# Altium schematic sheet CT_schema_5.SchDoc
size 257 x 245 mm
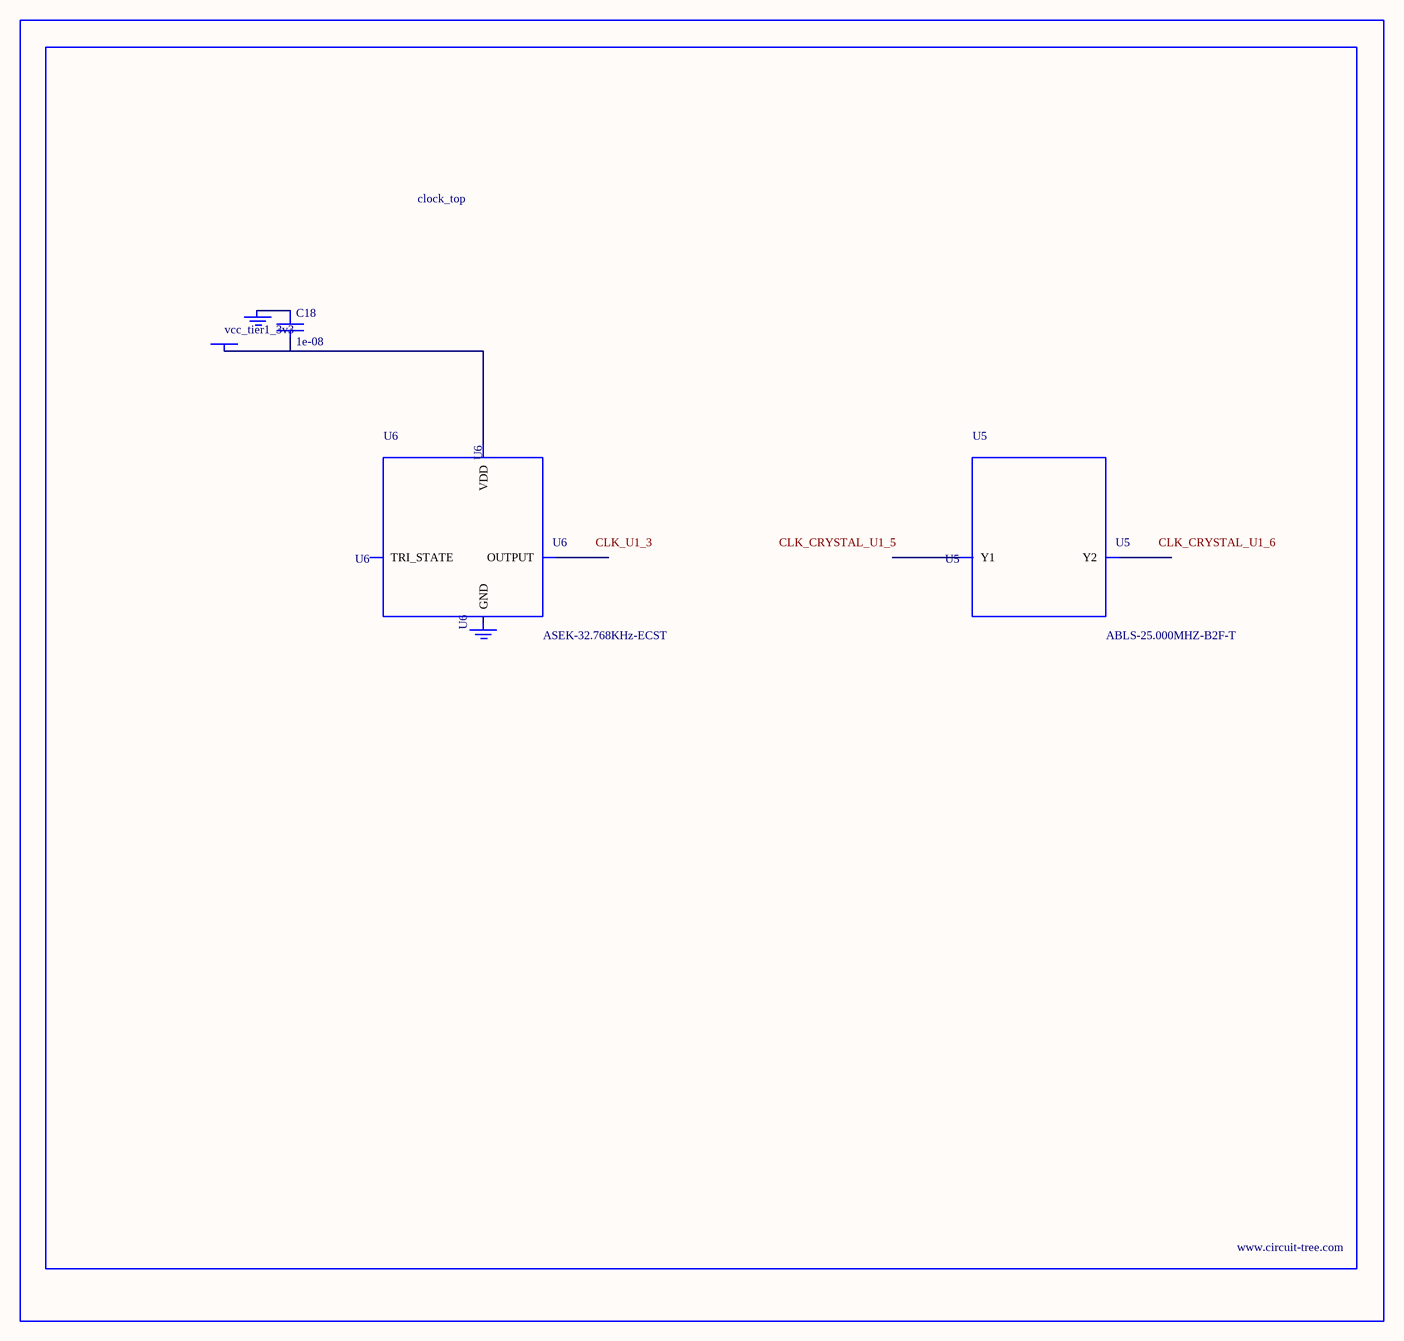
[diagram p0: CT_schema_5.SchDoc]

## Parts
BORDER4  (no value)
C18  1e-08  [C0402]
GND_INSTANCE_4_0  (no value)
GND_INSTANCE_4_1  (no value)
POWER_INSTANCE_4_0  vcc_tier1_3v3
U5  ABLS-25.000MHZ-B2F-T  [ABLS-25.000MHZ-B2F-T]
U6  ASEK-32.768KHz-ECST  [ASEK]

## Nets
NetC18_1: C18.1 GND_INSTANCE_4_0.0(GND)
NetC18_2: C18.2 POWER_INSTANCE_4_0.0(PWR) U6.4(VDD)

Not connected (* = marked no-connect by the designer): GND_INSTANCE_4_1 0(GND); U5 1(Y1) 2(Y2); U6 1(TRI_STATE) 2(GND) 3(OUTPUT)

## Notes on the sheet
- Labels drawn without touching a wire or pin: CLK_CRYSTAL_U1_5, CLK_CRYSTAL_U1_6, CLK_U1_3

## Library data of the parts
BORDER4 = BORDER_PAGE4
C18 = C0402C103K3RAC
GND_INSTANCE_4_0 GND_INSTANCE_4_1 = GND
POWER_INSTANCE_4_0 = PWR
